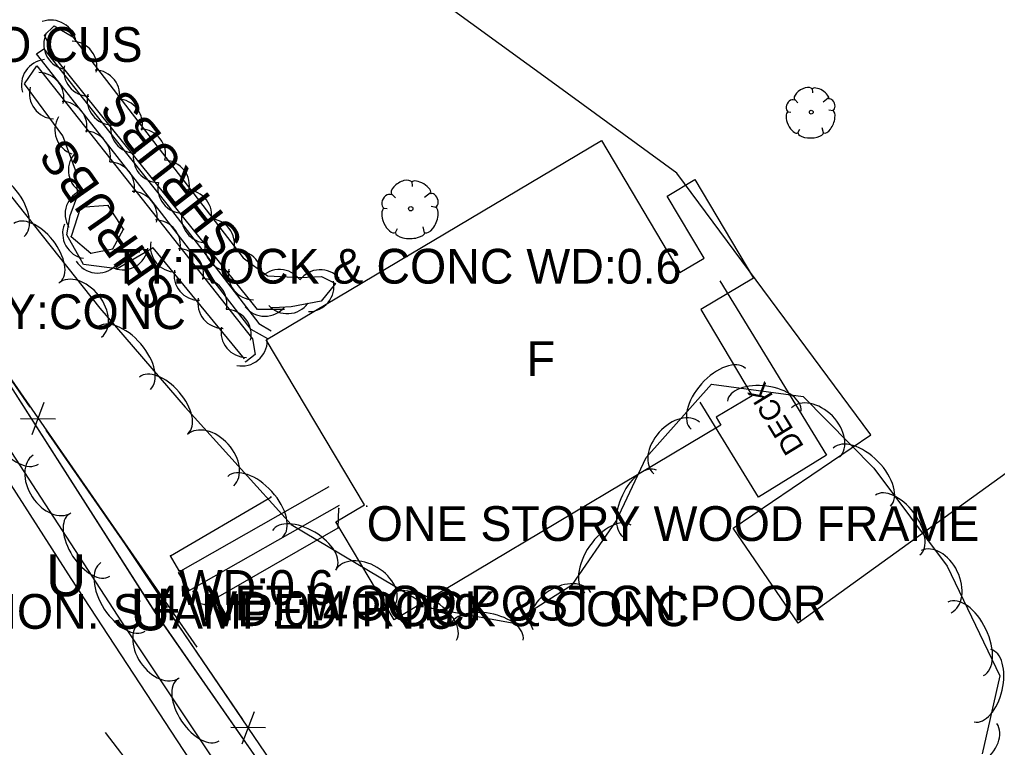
# Model space of a CAD drawing. Extents: x 954793 to 988390, y 1867850 to 1924428.
# Drawn here: x 965396.2 to 965536.8, y 1898944.4 to 1899049.1 of the extents above; entities that cross this region are included whole.
import ezdxf

# ---------------------------------------------------------------- set-up
doc = ezdxf.new("R2010")
doc.units = 0
for name, color, linetype in [('Default', 7, 'Continuous'), ('S_BUILDING', 7, 'Continuous'), ('S_BUILDING_ANNOT', 7, 'Continuous'), ('S_DITCHLINE', 7, 'Continuous'), ('S_DRIVEWAY', 7, 'Continuous'), ('S_FENCE', 7, 'Continuous'), ('S_FENCE_ANNOT', 7, 'Continuous'), ('S_FIBER_OPTIC_CABLE', 7, 'Continuous'), ('S_GRD_PT_SYM', 7, 'Continuous'), ('S_LANDSCAPING', 7, 'Continuous'), ('S_LANDSCAPING_ANNOT', 7, 'Continuous'), ('S_MISC_STRUCTURES', 7, 'Continuous'), ('S_MISC_STRUCTURES_ANNOT', 7, 'Continuous'), ('S_MSC_PT_SYM', 7, 'Continuous'), ('S_PRIMARY_CTL_ANNOT', 7, 'Continuous'), ('S_SIDEWALK', 7, 'Continuous'), ('S_SURVEY_TEXT_ANNOT', 7, 'Continuous'), ('S_TREE', 7, 'Continuous'), ('S_TREE_ANNOT', 7, 'Continuous'), ('S_UNDERGROUND_CABLE', 7, 'Continuous'), ('S_UTL_PT_SYM', 7, 'Continuous'), ('S_WATER_WELL_ANNOT', 7, 'Continuous')]:
    doc.layers.add(name, color=color, linetype=linetype)

msp = doc.modelspace()

# ---------------------------------------------------------------- linework, layer by layer
at = {"layer": 'S_BUILDING'}
msp.add_lwpolyline([(965497.02, 1898990.75), (965450.06, 1898962.79), (965441.69, 1898976.84), (965445.8, 1898979.29), (965431.69, 1899003.01), (965479.86, 1899031.69), (965491.15, 1899012.73), (965494.62, 1899014.79), (965489.32, 1899023.7), (965493.29, 1899026.07), (965501.72, 1899011.91), (965494.14, 1899007.39), (965501.53, 1898994.98), (965496.34, 1898991.89)], close=True, dxfattribs=at)
at = {"layer": 'S_DITCHLINE'}
msp.add_lwpolyline([(965444.1, 1898896.29), (965435.46, 1898909.55), (965426.81, 1898922.82), (965417.68, 1898934.7), (965408.56, 1898946.59)], dxfattribs=at)
at = {"layer": 'S_DRIVEWAY'}
msp.add_lwpolyline([(965554.2, 1898995.49), (965508.12, 1898962.28), (965498.81, 1898975.95), (965518.59, 1898989.36), (965490.69, 1899027.01), (965473.18, 1899039.8), (965457.09, 1899051.48)], dxfattribs=at)
msp.add_ellipse((965505.18, 1899028.58), major_axis=(-19.99, 36.37), ratio=0.992442, start_param=4.640192, end_param=5.70475, dxfattribs=at)
at = {"layer": 'S_FENCE'}
for p, q in [((965399.74, 1898994.04), (965398.01, 1898989.35)), ((965396.37, 1898991.7), (965401.38, 1898991.68)), ((965411.42, 1898973.62), (965417.43, 1898964.53)), ((965443.88, 1898925.56), (965417.54, 1898964.25)), ((965428.22, 1898944.92), (965429.99, 1898949.6)), ((965431.6, 1898947.23), (965426.6, 1898947.3))]:
    msp.add_line(p, q, dxfattribs=at)
for points in [[(965386.33, 1899009.77), (965397.73, 1898993.34)], [(965386.33, 1899009.77), (965421.69, 1898958.82)], [(965400.02, 1898990.05), (965411.42, 1898973.62)], [(965428.3, 1898948.45), (965417.54, 1898964.25)]]:
    msp.add_lwpolyline(points, dxfattribs=at)
at = {"layer": 'S_FIBER_OPTIC_CABLE'}
for p, q in [((965415.76, 1898963.81), (965355.43, 1899058)), ((965461.5, 1898898.15), (965415.76, 1898963.81))]:
    msp.add_line(p, q, dxfattribs=at)
at = {"layer": 'S_GRD_PT_SYM'}
for points in [[(965405, 1899022.04), (965405, 1899022.09), (965405, 1899022.04), (965404.95, 1899022.04), (965405, 1899022.04), (965405, 1899021.99), (965405, 1899022.04), (965405.05, 1899022.04)], [(965408.97, 1899022.32), (965408.97, 1899022.37), (965408.97, 1899022.32), (965408.92, 1899022.32), (965408.97, 1899022.32), (965408.97, 1899022.27), (965408.97, 1899022.32), (965409.02, 1899022.32)], [(965411.19, 1899018.95), (965411.19, 1899019), (965411.19, 1899018.95), (965411.14, 1899018.95), (965411.19, 1899018.95), (965411.19, 1899018.9), (965411.19, 1899018.95), (965411.24, 1899018.95)], [(965403.66, 1899017.9), (965403.66, 1899017.95), (965403.66, 1899017.9), (965403.61, 1899017.9), (965403.66, 1899017.9), (965403.66, 1899017.85), (965403.66, 1899017.9), (965403.71, 1899017.9)], [(965406.45, 1899015.47), (965406.45, 1899015.52), (965406.45, 1899015.47), (965406.4, 1899015.47), (965406.45, 1899015.47), (965406.45, 1899015.42), (965406.45, 1899015.47), (965406.5, 1899015.47)], [(965409.63, 1899016.11), (965409.63, 1899016.16), (965409.63, 1899016.11), (965409.58, 1899016.11), (965409.63, 1899016.11), (965409.63, 1899016.06), (965409.63, 1899016.11), (965409.68, 1899016.11)], [(965432.36, 1898980.43), (965432.36, 1898980.48), (965432.36, 1898980.43), (965432.31, 1898980.43), (965432.36, 1898980.43), (965432.36, 1898980.38), (965432.36, 1898980.43), (965432.41, 1898980.43)], [(965442.11, 1898978.76), (965442.11, 1898978.81), (965442.11, 1898978.76), (965442.06, 1898978.76), (965442.11, 1898978.76), (965442.11, 1898978.71), (965442.11, 1898978.76), (965442.16, 1898978.76)], [(965442.04, 1898976.02), (965442.04, 1898976.07), (965442.04, 1898976.02), (965441.99, 1898976.02), (965442.04, 1898976.02), (965442.04, 1898975.97), (965442.04, 1898976.02), (965442.09, 1898976.02)], [(965417.91, 1898971.96), (965417.91, 1898972.01), (965417.91, 1898971.96), (965417.86, 1898971.96), (965417.91, 1898971.96), (965417.91, 1898971.91), (965417.91, 1898971.96), (965417.96, 1898971.96)], [(965419.1, 1898969.92), (965419.1, 1898969.97), (965419.1, 1898969.92), (965419.05, 1898969.92), (965419.1, 1898969.92), (965419.1, 1898969.87), (965419.1, 1898969.92), (965419.15, 1898969.92)], [(965421.19, 1898966.86), (965421.19, 1898966.91), (965421.19, 1898966.86), (965421.14, 1898966.86), (965421.19, 1898966.86), (965421.19, 1898966.81), (965421.19, 1898966.86), (965421.24, 1898966.86)], [(965422.1, 1898965.16), (965422.1, 1898965.21), (965422.1, 1898965.16), (965422.05, 1898965.16), (965422.1, 1898965.16), (965422.1, 1898965.11), (965422.1, 1898965.16), (965422.15, 1898965.16)], [(965422.88, 1898964.97), (965422.88, 1898965.02), (965422.88, 1898964.97), (965422.83, 1898964.97), (965422.88, 1898964.97), (965422.88, 1898964.92), (965422.88, 1898964.97), (965422.93, 1898964.97)]]:
    msp.add_lwpolyline(points, dxfattribs=at)
at = {"layer": 'S_LANDSCAPING'}
for p, q in [((965405, 1899022.04), (965403.66, 1899017.9)), ((965408.97, 1899022.32), (965405, 1899022.04)), ((965411.19, 1899018.95), (965408.97, 1899022.32)), ((965403.66, 1899017.9), (965406.45, 1899015.47)), ((965409.63, 1899016.11), (965411.19, 1899018.95)), ((965406.45, 1899015.47), (965409.63, 1899016.11)), ((965417.91, 1898971.96), (965432.36, 1898980.43)), ((965442.04, 1898976.02), (965442.11, 1898978.76)), ((965422.88, 1898964.97), (965442.04, 1898976.02)), ((965419.1, 1898969.92), (965417.91, 1898971.96)), ((965421.19, 1898966.86), (965422.1, 1898965.16)), ((965422.1, 1898965.16), (965422.88, 1898964.97))]:
    msp.add_line(p, q, dxfattribs=at)
at = {"layer": 'S_MISC_STRUCTURES'}
msp.add_lwpolyline([(965496.87, 1899011.51), (965512.23, 1898986.46), (965502.45, 1898980.43), (965494.06, 1898994.05)], dxfattribs=at)
at = {"layer": 'S_MSC_PT_SYM'}
for points in [[(965446.12, 1898979.11), (965446.12, 1898979.16), (965446.12, 1898979.11), (965446.07, 1898979.11), (965446.12, 1898979.11), (965446.12, 1898979.06), (965446.12, 1898979.11), (965446.17, 1898979.11)], [(965415.46, 1898967.68), (965415.46, 1898967.73), (965415.46, 1898967.68), (965415.41, 1898967.68), (965415.46, 1898967.68), (965415.46, 1898967.63), (965415.46, 1898967.68), (965415.51, 1898967.68)], [(965417.54, 1898964.25), (965417.54, 1898964.3), (965417.54, 1898964.25), (965417.49, 1898964.25), (965417.54, 1898964.25), (965417.54, 1898964.2), (965417.54, 1898964.25), (965417.59, 1898964.25)]]:
    msp.add_lwpolyline(points, dxfattribs=at)
at = {"layer": 'S_SIDEWALK'}
for points in [[(965431.92, 1899003.15), (965429.5, 1899004.53), (965416.65, 1899021.26), (965407.66, 1899032.71), (965398.67, 1899044.16), (965399.7, 1899044.86), (965408.65, 1899033.57), (965417.6, 1899022.27), (965430.64, 1899005.37), (965432.41, 1899004.34)], [(965440.68, 1898981.9), (965419.04, 1898969.6), (965420.63, 1898966.97), (965442.23, 1898979.28)]]:
    msp.add_lwpolyline(points, dxfattribs=at)
at = {"layer": 'S_TREE'}
for p, q in [((965510.14, 1899039.2), (965510.19, 1899038.53)), ((965507.67, 1899037.56), (965508.1, 1899037.1)), ((965512.45, 1899037.75), (965511.74, 1899037.2)), ((965513.18, 1899035.95), (965512.57, 1899036.07)), ((965506.58, 1899035.8), (965507.08, 1899035.76)), ((965508.11, 1899032.81), (965508.4, 1899033.3)), ((965511.76, 1899032.79), (965511.58, 1899033.52)), ((965452.63, 1899025.84), (965452.68, 1899025.06)), ((965449.76, 1899023.96), (965450.25, 1899023.43)), ((965455.28, 1899024.15), (965454.45, 1899023.51)), ((965448.49, 1899021.94), (965449.07, 1899021.89)), ((965456.11, 1899022.06), (965455.41, 1899022.21)), ((965450.24, 1899018.48), (965450.57, 1899019.05)), ((965454.44, 1899018.43), (965454.25, 1899019.28))]:
    msp.add_line(p, q, dxfattribs=at)
for points in [[(965434.3, 1899007.38), (965430.43, 1899007.4), (965429.45, 1899008.57), (965401.39, 1899043.51), (965399.83, 1899046.84), (965401.22, 1899048.17), (965403.87, 1899046.58), (965428.37, 1899014.82), (965431.85, 1899012.21), (965436.57, 1899012.01), (965439.62, 1899012.14), (965441.66, 1899011.14), (965439.57, 1899008.6), (965435.25, 1899007.79), (965433.57, 1899007.69), (965432.32, 1899007.64)], [(965428.57, 1899000.28), (965415.42, 1899016.26), (965410.28, 1899013.23), (965405.43, 1899013.84), (965403.03, 1899018.14), (965403.52, 1899020.9), (965404.59, 1899023.86), (965404.25, 1899027.43), (965402.45, 1899032.36), (965396.96, 1899039.84), (965398.69, 1899042.44), (965429.72, 1899003.19), (965430.11, 1899000.94), (965428.76, 1898999.85), (965428.63, 1898999.81)], [(965432.98, 1898929.44), (965410.91, 1898962.5), (965393.89, 1898988.74), (965378.75, 1899010.52), (965368.28, 1899026.21), (965367.8, 1899032.05), (965374.03, 1899037.03), (965386.87, 1899033.92), (965395.98, 1899022.43), (965407.78, 1899007.57), (965420.01, 1898993.37), (965435.26, 1898976.5), (965455.48, 1898964.45), (965467.01, 1898962.32), (965475.72, 1898967.86), (965481.96, 1898976.96), (965486.29, 1898986.12), (965495.69, 1898996.66), (965508.88, 1898994.88), (965519.01, 1898984.57), (965529.54, 1898970.47), (965537.14, 1898954.73), (965534.58, 1898943.51)]]:
    msp.add_lwpolyline(points, dxfattribs=at)
for centre, radius in [((965510.02, 1899035.77), 0.274), ((965452.46, 1899021.88), 0.316)]:
    msp.add_circle(centre, radius, dxfattribs=at)
for centre, start, end in [((965400.74, 1899045.36), 8.3166, 109.9135), ((965403.35, 1899045.52), 154.3017, 255.8986), ((965403.71, 1899042.32), 346.8474, 88.4443), ((965400.15, 1899039.69), 95.5662, 197.1632), ((965406.23, 1899041.68), 167.9738, 269.5707), ((965406.99, 1899038.18), 346.8474, 88.4443), ((965398.96, 1899037.81), 347.5309, 89.1278), ((965401.29, 1899038.44), 165.4976, 267.0945), ((965402.28, 1899033.67), 347.5309, 89.1278), ((965409.58, 1899037.57), 167.9738, 269.5707), ((965410.26, 1899034.01), 346.8474, 88.4443), ((965404.94, 1899033.21), 149.2642, 250.8611), ((965405.65, 1899029.4), 347.5309, 89.1278), ((965412.94, 1899033.49), 167.9738, 269.5707), ((965413.58, 1899029.7), 346.8474, 88.4443), ((965406.89, 1899027.43), 134.6178, 236.2147), ((965416.22, 1899029.29), 167.9738, 269.5707), ((965417, 1899025.2), 346.8474, 88.4443), ((965409.13, 1899024.95), 347.5309, 89.1278), ((965419.74, 1899024.87), 167.9738, 269.5707), ((965406.42, 1899021.1), 109.3763, 210.9732), ((965412.38, 1899020.72), 347.5309, 89.1278), ((965420.2, 1899020.94), 346.8474, 88.4443), ((965423.14, 1899020.62), 167.9738, 269.5707), ((965423.49, 1899016.8), 346.8474, 88.4443), ((965406.06, 1899018.33), 158.2895, 259.8864), ((965415.71, 1899016.62), 347.5309, 89.1278), ((965411.07, 1899016.74), 249.7348, 351.3317), ((965418.68, 1899016.42), 168.6391, 270.236), ((965426.49, 1899016.51), 167.9738, 269.5707), ((965419.03, 1899012.48), 347.5309, 89.1278), ((965427.4, 1899012.27), 2.2791, 103.876), ((965407.46, 1899016.26), 211.9883, 313.5852), ((965422.08, 1899012.35), 168.6391, 270.236), ((965429.86, 1899012.44), 167.9738, 269.5707), ((965433.59, 1899009.5), 36.8142, 138.4111), ((965439.45, 1899009.47), 41.603, 143.1999), ((965422.4, 1899008.21), 347.5309, 89.1278), ((965437.78, 1899010.72), 269.8379, 11.4348), ((965425.49, 1899008.32), 168.6391, 270.236), ((965431.49, 1899010.06), 218.948, 320.545), ((965434.72, 1899010.43), 222.4942, 324.0911), ((965425.88, 1899003.76), 347.5309, 89.1278), ((965428.83, 1899004.15), 168.6391, 270.236), ((965428.2, 1899002.92), 258.3805, 359.9774)]:
    msp.add_arc(centre, 3.64, start, end, dxfattribs=at)
for centre, major_axis, ratio, start_param, end_param in [((965508.88, 1899038.29), (1.26, 0.78), 0.529943, 0, 3.141593), ((965511.32, 1899038.37), (1.18, -0.71), 0.420543, 6.283185, 9.424777), ((965507.14, 1899036.65), (-0.466, -0.833), 0.711534, 3.141592, 6.283185), ((965512.83, 1899036.84), (0.312, -0.804), 0.646762, 0, 3.141593), ((965512.45, 1899034.39), (-0.65, -1.61), 0.471018, 0, 3.141593), ((965507.42, 1899034.29), (0.72, -1.52), 0.482994, 3.141593, 6.283185), ((965509.96, 1899032.79), (1.82, 0.03), 0.405113, 3.141593, 6.283186), ((965393.23, 1899022.49), (-3.65, 4.6), 0.55008, 3.141593, 6.283185), ((965451.16, 1899024.8), (1.46, 0.89), 0.529943, 0, 3.141593), ((965453.98, 1899024.87), (1.35, -0.83), 0.420543, 6.283185, 9.424777), ((965449.15, 1899022.91), (-0.544, -0.957), 0.711534, 3.141592, 6.283185), ((965455.71, 1899023.09), (0.354, -0.93), 0.646762, 0, 3.141593), ((965449.45, 1899020.2), (0.81, -1.76), 0.482994, 3.141593, 6.283185), ((965455.25, 1899020.27), (-0.76, -1.85), 0.471018, 0, 3.141593), ((965398.74, 1899015.54), (-3.33, 4.19), 0.540699, 3.141593, 6.283185), ((965452.37, 1899018.45), (2.11, 0.02), 0.405113, 3.141593, 6.283186), ((965404.95, 1899007.31), (-3.08, 3.88), 0.685311, 3.141593, 6.283185), ((965411.2, 1899000.35), (-3.83, 4.45), 0.55008, 3.141593, 6.283185), ((965496.65, 1898994.55), (-3.9, -4.38), 0.55008, 3.141593, 6.283185), ((965416.98, 1898993.63), (-3.49, 4.05), 0.540699, 3.141593, 6.283185), ((965503.26, 1898993.5), (-5.3, 0.72), 0.540699, 3.141593, 6.283185), ((965395.6, 1898989.99), (3.35, -4.82), 0.55008, 3.141593, 6.283185), ((965510.63, 1898989.7), (-3.47, 3.54), 0.685311, 3.141593, 6.283185), ((965490.68, 1898987.47), (-3.3, -3.7), 0.685311, 3.141593, 6.283185), ((965423.69, 1898985.74), (-3.32, 3.68), 0.685311, 3.141593, 6.283185), ((965517.3, 1898983.28), (-4.11, 4.19), 0.55008, 3.141593, 6.283185), ((965400.9, 1898982.31), (2.7, -4.16), 0.685311, 3.141593, 6.283185), ((965430.1, 1898979.05), (-3.94, 4.35), 0.55008, 3.141593, 6.283185), ((965485.48, 1898979.45), (-2.29, -4.83), 0.540699, 3.141593, 6.283185), ((965522.45, 1898976.41), (-3.2, 4.28), 0.540699, 3.141593, 6.283185), ((965406.29, 1898973.52), (2.91, -4.49), 0.540699, 3.141593, 6.283185), ((965437.19, 1898972.88), (-4.59, 2.74), 0.540699, 3.141593, 6.283185), ((965480.82, 1898971.54), (-3.32, -4.84), 0.55008, 3.141593, 6.283185), ((965527.96, 1898968.26), (-2.16, 4.46), 0.685311, 3.141593, 6.283185), ((965445.91, 1898967.38), (-4.26, 2.54), 0.685311, 3.141593, 6.283185), ((965411.11, 1898966.08), (3.19, -4.92), 0.55008, 3.141593, 6.283185), ((965474.18, 1898964.06), (-4.18, -2.66), 0.685311, 3.141593, 6.283185), ((965454, 1898962.86), (-5.04, 3.01), 0.55008, 3.141593, 6.283185), ((965532.22, 1898960.04), (-2.55, 5.28), 0.55008, 3.141593, 6.283185), ((965463.36, 1898960.84), (-5.26, 0.97), 0.540699, 3.141593, 6.283185), ((965416.43, 1898958.53), (2.75, -4.12), 0.685311, 3.141593, 6.283185), ((965534.64, 1898953.31), (1.19, 5.21), 0.540699, 3.141593, 6.283185), ((965421.93, 1898949.82), (2.97, -4.45), 0.540699, 3.141593, 6.283185), ((965532.62, 1898945.06), (4.08, 2.81), 0.685311, 3.141593, 6.283185)]:
    msp.add_ellipse(centre, major_axis=major_axis, ratio=ratio, start_param=start_param, end_param=end_param, dxfattribs=at)
at = {"layer": 'S_UNDERGROUND_CABLE'}
for p, q in [((965403.66, 1898968.71), (965345.13, 1899059.93)), ((965415.78, 1898963.8), (965355.43, 1899058)), ((965478.11, 1898854.97), (965403.66, 1898968.71)), ((965461.51, 1898898.15), (965415.78, 1898963.8))]:
    msp.add_line(p, q, dxfattribs=at)
at = {"layer": 'S_UTL_PT_SYM'}
msp.add_lwpolyline([(965415.76, 1898963.81), (965415.76, 1898963.86), (965415.76, 1898963.81), (965415.71, 1898963.81), (965415.76, 1898963.81), (965415.76, 1898963.76), (965415.76, 1898963.81), (965415.81, 1898963.81)], dxfattribs=at)

# ---------------------------------------------------------------- texts
at = {"layer": 'Default'}
for p in [(965400.03, 1898966.17), (965412.15, 1898961.26)]:
    msp.add_text('U', height=6, rotation=360, dxfattribs=at).set_placement(p)
at = {"layer": 'S_BUILDING_ANNOT'}
msp.add_text('F', height=5, dxfattribs=at).set_placement((965469.11, 1898997.82))
at = {"layer": 'S_FENCE_ANNOT'}
msp.add_text("4' NET WOOD POST CN:POOR", height=5, dxfattribs=at).set_placement((965415.46, 1898962.68))
at = {"layer": 'S_LANDSCAPING_ANNOT'}
for s, p in [('TY:ROCK & CONC WD:0.6', (965409.63, 1899011.11)), ('WD:0.6', (965419.1, 1898964.92)), ('WD:0.4 ROCK & CONC', (965421.19, 1898961.86))]:
    msp.add_text(s, height=5, dxfattribs=at).set_placement(p)
at = {"layer": 'S_MISC_STRUCTURES_ANNOT'}
msp.add_text('DECK', height=3, rotation=121.3321, dxfattribs=at).set_placement((965509.05, 1898987.67))
at = {"layer": 'S_PRIMARY_CTL_ANNOT'}
msp.add_text('PD:ARDOT STD. MON. STAMPED PN:39', height=5, dxfattribs=at).set_placement((965336.79, 1898961.48))
at = {"layer": 'S_SURVEY_TEXT_ANNOT'}
for s, p in [('GRAVEL DW NO CUS', (965345.92, 1899042.99)), ('ONE STORY WOOD FRAME', (965446.12, 1898974.11))]:
    msp.add_text(s, height=5, dxfattribs=at).set_placement(p)
at = {"layer": 'S_TREE_ANNOT'}
for rotation, p in [(127.8565, (965428.57, 1899017.35)), (124.9941, (965418.86, 1899009.55))]:
    msp.add_text('SHRUBS', height=5, rotation=rotation, dxfattribs=at).set_placement(p)
at = {"layer": 'S_WATER_WELL_ANNOT'}
msp.add_text('TY:CONC', height=5, dxfattribs=at).set_placement((965390.05, 1899004.57))

doc.saveas('drawing.dxf')
